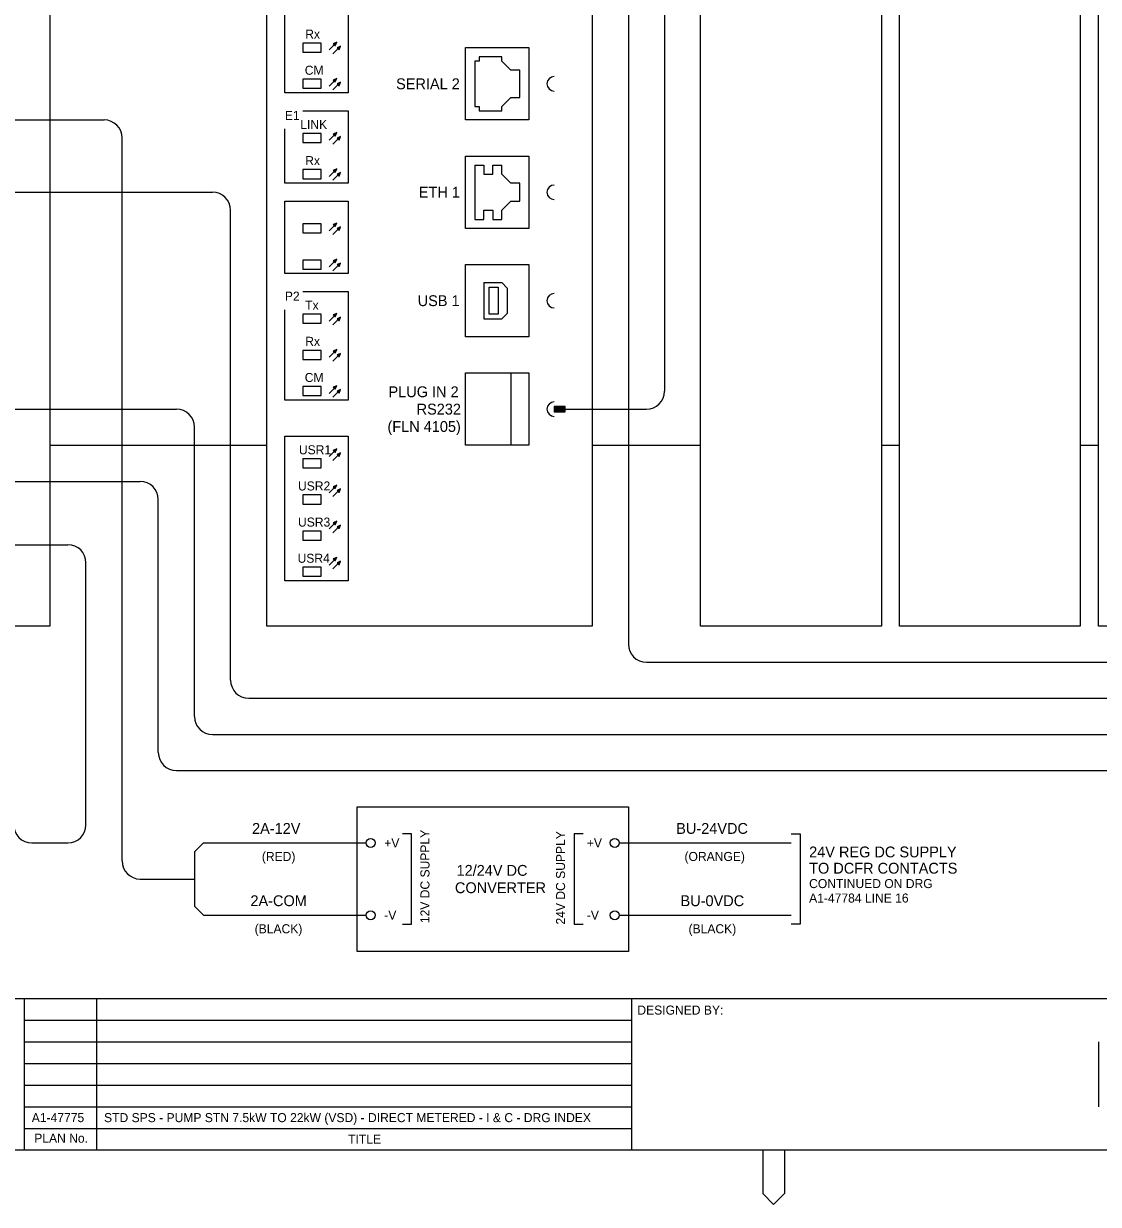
# Model space of a CAD drawing. Extents: x 0 to 841, y 0 to 594.
# Drawn here: x 212.8 to 510, y 0 to 326.6 of the extents above; entities that cross this region are included whole.
import ezdxf

# ---------------------------------------------------------------- set-up
doc = ezdxf.new("R2010")
doc.units = 0
for name, color, linetype in [('A1BORDER', 7, 'Continuous'), ('Level 1', 7, 'Continuous'), ('Level 10', 7, 'Continuous'), ('Level 5', 7, 'Continuous')]:
    doc.layers.add(name, color=color, linetype=linetype)

msp = doc.modelspace()

# ---------------------------------------------------------------- linework, layer by layer
at = {"layer": 'A1BORDER'}
for p, q in [((28, 57), (829, 57)), ((213, 15), (213, 57)), ((233, 15), (233, 57)), ((381, 15), (381, 57)), ((213, 51), (381, 51)), ((213, 45), (381, 45)), ((213, 39), (381, 39)), ((213, 33), (381, 33)), ((213, 27), (381, 27)), ((213, 21), (381, 21)), ((829, 15), (28, 15)), ((417.19, 15), (417.19, 3)), ((423.19, 15), (423.19, 3)), ((417.19, 3), (420.19, 0)), ((423.19, 3), (420.19, 0))]:
    msp.add_line(p, q, dxfattribs=at)
at = {"layer": 'Level 1'}
for p, q in [((390, 555), (390, 225)), ((380, 340), (380, 155)), ((345, 317.5), (338.75, 317.5)), ((338.75, 317.5), (338.75, 316.25)), ((345, 316.25), (345, 317.5)), ((337.5, 316.25), (337.5, 303.75)), ((338.75, 316.25), (337.5, 316.25)), ((345, 316.25), (347.5, 313.75)), ((350, 313.75), (347.5, 313.75)), ((350, 306.25), (350, 313.75)), ((345, 303.75), (347.5, 306.25)), ((347.5, 306.25), (350, 306.25)), ((337.5, 303.75), (338.75, 303.75)), ((338.75, 303.75), (338.75, 302.5)), ((338.75, 302.5), (345, 302.5)), ((345, 302.5), (345, 303.75)), ((207.5, 300), (235, 300)), ((240, 95), (240, 295)), ((337.5, 287.5), (337.5, 272.5)), ((337.5, 287.5), (340, 287.5)), ((340, 287.5), (340, 285)), ((342.5, 285), (342.5, 287.5)), ((342.5, 287.5), (345, 287.5)), ((345, 285), (345, 287.5)), ((340, 285), (342.5, 285)), ((345, 285), (347.5, 282.5)), ((350, 282.5), (347.5, 282.5)), ((350, 277.5), (350, 282.5)), ((207.5, 280), (265, 280)), ((270, 145), (270, 275)), ((340, 272.5), (340, 275)), ((340, 275), (342.5, 275)), ((342.5, 275), (342.5, 272.5)), ((345, 275), (347.5, 277.5)), ((345, 272.5), (345, 275)), ((347.5, 277.5), (350, 277.5)), ((337.5, 272.5), (340, 272.5)), ((342.5, 272.5), (345, 272.5)), ((340, 255), (340, 245)), ((340, 255), (345, 255)), ((345, 255), (346.5, 253.5)), ((346.5, 253.5), (346.5, 246.5)), ((340, 245), (345, 245)), ((345, 245), (346.5, 246.5)), ((347.5, 230), (347.5, 210)), ((207.5, 220), (255, 220)), ((362.5, 220), (385, 220)), ((260, 135), (260, 215)), ((220, 210), (280, 210)), ((370, 210), (400, 210)), ((450, 210), (455, 210)), ((505, 210), (510, 210)), ((207.5, 200), (245, 200)), ((250, 125), (250, 195)), ((207.5, 182.5), (225, 182.5)), ((230, 105), (230, 177.5)), ((385, 150), (585, 150)), ((275, 140), (595, 140)), ((265, 130), (605, 130)), ((255, 120), (685, 120)), ((215, 100), (225, 100)), ((262.5, 100), (260, 97.5)), ((262.5, 100), (307.5, 100)), ((377.5, 100), (425, 100)), ((260, 97.5), (260, 82.5)), ((245, 90), (260.01, 90)), ((262.5, 80), (260, 82.5)), ((262.5, 80), (307.5, 80)), ((377.5, 80), (425, 80))]:
    msp.add_line(p, q, dxfattribs=at)
for points in [[(140, 510), (220, 510), (220, 160), (140, 160)], [(280, 510), (370, 510), (370, 160), (280, 160)], [(400, 510), (450, 510), (450, 160), (400, 160)], [(455, 510), (505, 510), (505, 160), (455, 160)], [(510, 510), (560, 510), (560, 160), (510, 160)], [(295, 321.25), (290, 321.25), (290, 318.75), (295, 318.75)], [(335, 320), (352.5, 320), (352.5, 300), (335, 300)], [(295, 311.25), (290, 311.25), (290, 308.75), (295, 308.75)], [(295, 296.25), (290, 296.25), (290, 293.75), (295, 293.75)], [(335, 290), (352.5, 290), (352.5, 270), (335, 270)], [(295, 286.25), (290, 286.25), (290, 283.75), (295, 283.75)], [(285, 277.5), (302.5, 277.5), (302.5, 257.5), (285, 257.5)], [(295, 271.25), (290, 271.25), (290, 268.75), (295, 268.75)], [(295, 261.25), (290, 261.25), (290, 258.75), (295, 258.75)], [(335, 260), (352.5, 260), (352.5, 240), (335, 240)], [(341.5, 253.75), (344, 253.75), (344, 246.25), (341.5, 246.25)], [(295, 246.25), (290, 246.25), (290, 243.75), (295, 243.75)], [(295, 236.25), (290, 236.25), (290, 233.75), (295, 233.75)], [(335, 230), (352.5, 230), (352.5, 210), (335, 210)], [(295, 226.25), (290, 226.25), (290, 223.75), (295, 223.75)], [(285, 212.5), (302.5, 212.5), (302.5, 172.5), (285, 172.5)], [(295, 206.25), (290, 206.25), (290, 203.75), (295, 203.75)], [(295, 196.25), (290, 196.25), (290, 193.75), (295, 193.75)], [(295, 186.25), (290, 186.25), (290, 183.75), (295, 183.75)], [(295, 176.25), (290, 176.25), (290, 173.75), (295, 173.75)], [(305, 110), (380, 110), (380, 70), (305, 70)]]:
    msp.add_lwpolyline(points, close=True, dxfattribs=at)
for points in [[(290, 337.5), (302.5, 337.5), (302.5, 307.5), (285, 307.5), (285, 332.5)], [(290, 302.5), (302.5, 302.5), (302.5, 282.5), (285, 282.5), (285, 297.5)], [(290, 252.5), (302.5, 252.5), (302.5, 222.5), (285, 222.5), (285, 247.5)], [(317.5, 77.5), (320, 77.5), (320, 102.5), (317.5, 102.5)], [(367.5, 102.5), (365, 102.5), (365, 77.5), (367.5, 77.5)], [(425, 102.5), (427.5, 102.5), (427.5, 77.5), (425, 77.5)]]:
    msp.add_lwpolyline(points, dxfattribs=at)
for centre, start, end in [((235, 295), 0, 90), ((265, 275), 0, 90), ((385, 225), 270, 0), ((255, 215), 0, 90), ((245, 195), 0, 90), ((225, 177.5), 0, 90), ((385, 155), 180, 270), ((275, 145), 180, 270), ((265, 135), 180, 270), ((255, 125), 180, 270), ((215, 105), 180, 270), ((225, 105), 270, 360), ((245, 95), 180, 270)]:
    msp.add_arc(centre, 5, start, end, dxfattribs=at)
at = {"layer": 'Level 10'}
for p, q in [((297.23, 319.36), (299.36, 321.48)), ((298.29, 318.3), (300.42, 320.42)), ((298.46, 321.07), (299.17, 321.07)), ((298.5, 320.93), (299.11, 320.93)), ((298.64, 320.78), (299.04, 320.78)), ((298.79, 321.23), (299.24, 321.23)), ((298.8, 320.62), (298.97, 320.62)), ((299.12, 321.38), (299.31, 321.38)), ((299.85, 320.17), (300.3, 320.17)), ((300.18, 320.31), (300.37, 320.31)), ((299.52, 320.01), (300.23, 320.01)), ((299.56, 319.87), (300.17, 319.87)), ((299.7, 319.72), (300.1, 319.72)), ((299.86, 319.56), (300.03, 319.56)), ((297.23, 309.36), (299.36, 311.48)), ((298.29, 308.3), (300.42, 310.42)), ((298.46, 311.07), (299.17, 311.07)), ((298.5, 310.93), (299.11, 310.93)), ((298.64, 310.78), (299.04, 310.78)), ((298.79, 311.23), (299.24, 311.23)), ((298.8, 310.62), (298.97, 310.62)), ((299.12, 311.38), (299.31, 311.38)), ((299.52, 310.01), (300.23, 310.01)), ((299.56, 309.87), (300.17, 309.87)), ((299.7, 309.72), (300.1, 309.72)), ((299.85, 310.17), (300.3, 310.17)), ((299.86, 309.56), (300.03, 309.56)), ((300.18, 310.31), (300.37, 310.31)), ((297.23, 294.36), (299.36, 296.48)), ((298.29, 293.3), (300.42, 295.42)), ((298.46, 296.07), (299.17, 296.07)), ((298.5, 295.93), (299.11, 295.93)), ((298.64, 295.78), (299.04, 295.78)), ((298.79, 296.23), (299.24, 296.23)), ((298.8, 295.62), (298.97, 295.62)), ((299.12, 296.38), (299.31, 296.38)), ((299.52, 295.01), (300.23, 295.01)), ((299.56, 294.87), (300.17, 294.87)), ((299.7, 294.72), (300.1, 294.72)), ((299.85, 295.17), (300.3, 295.17)), ((299.86, 294.56), (300.03, 294.56)), ((300.18, 295.31), (300.37, 295.31)), ((297.23, 284.36), (299.36, 286.48)), ((298.29, 283.3), (300.42, 285.42)), ((298.46, 286.07), (299.17, 286.07)), ((298.5, 285.93), (299.11, 285.93)), ((298.64, 285.78), (299.04, 285.78)), ((298.79, 286.23), (299.24, 286.23)), ((298.8, 285.62), (298.97, 285.62)), ((299.12, 286.38), (299.31, 286.38)), ((299.52, 285.01), (300.23, 285.01)), ((299.56, 284.87), (300.17, 284.87)), ((299.7, 284.72), (300.1, 284.72)), ((299.85, 285.17), (300.3, 285.17)), ((299.86, 284.56), (300.03, 284.56)), ((300.18, 285.31), (300.37, 285.31)), ((297.23, 269.36), (299.36, 271.48)), ((298.79, 271.23), (299.24, 271.23)), ((299.12, 271.38), (299.31, 271.38)), ((298.29, 268.3), (300.42, 270.42)), ((298.46, 271.07), (299.17, 271.07)), ((298.5, 270.93), (299.11, 270.93)), ((298.64, 270.77), (299.04, 270.77)), ((298.8, 270.62), (298.97, 270.62)), ((299.52, 270.01), (300.23, 270.01)), ((299.56, 269.87), (300.17, 269.87)), ((299.7, 269.72), (300.1, 269.72)), ((299.85, 270.17), (300.3, 270.17)), ((299.86, 269.56), (300.03, 269.56)), ((300.18, 270.31), (300.37, 270.31)), ((297.23, 259.36), (299.36, 261.48)), ((299.12, 261.38), (299.31, 261.38)), ((298.29, 258.3), (300.42, 260.42)), ((298.46, 261.07), (299.17, 261.07)), ((298.5, 260.93), (299.11, 260.93)), ((298.64, 260.77), (299.04, 260.77)), ((298.79, 261.23), (299.24, 261.23)), ((298.8, 260.62), (298.97, 260.62)), ((299.52, 260.01), (300.23, 260.01)), ((299.56, 259.87), (300.17, 259.87)), ((299.7, 259.72), (300.1, 259.72)), ((299.85, 260.17), (300.3, 260.17)), ((299.86, 259.56), (300.03, 259.56)), ((300.18, 260.31), (300.37, 260.31)), ((297.23, 244.36), (299.36, 246.48)), ((298.29, 243.3), (300.42, 245.42)), ((298.46, 246.08), (299.17, 246.08)), ((298.5, 245.93), (299.11, 245.93)), ((298.64, 245.78), (299.04, 245.78)), ((298.79, 246.22), (299.24, 246.22)), ((298.8, 245.62), (298.97, 245.62)), ((299.12, 246.38), (299.31, 246.38)), ((299.52, 245.02), (300.23, 245.02)), ((299.85, 245.16), (300.3, 245.16)), ((300.18, 245.31), (300.37, 245.31)), ((299.56, 244.87), (300.17, 244.87)), ((299.7, 244.72), (300.1, 244.72)), ((299.86, 244.56), (300.03, 244.56)), ((297.23, 234.36), (299.36, 236.48)), ((298.29, 233.3), (300.42, 235.42)), ((298.46, 236.08), (299.17, 236.08)), ((298.5, 235.93), (299.11, 235.93)), ((298.64, 235.78), (299.04, 235.78)), ((298.79, 236.22), (299.24, 236.22)), ((298.8, 235.62), (298.97, 235.62)), ((299.12, 236.38), (299.31, 236.38)), ((300.18, 235.31), (300.37, 235.31)), ((299.52, 235.02), (300.23, 235.02)), ((299.56, 234.87), (300.17, 234.87)), ((299.7, 234.72), (300.1, 234.72)), ((299.85, 235.16), (300.3, 235.16)), ((299.86, 234.56), (300.03, 234.56)), ((297.23, 224.36), (299.36, 226.48)), ((298.29, 223.3), (300.42, 225.42)), ((298.46, 226.08), (299.17, 226.08)), ((298.5, 225.93), (299.11, 225.93)), ((298.64, 225.78), (299.04, 225.78)), ((298.79, 226.22), (299.24, 226.22)), ((298.8, 225.62), (298.97, 225.62)), ((299.12, 226.38), (299.31, 226.38)), ((299.52, 225.02), (300.23, 225.02)), ((299.56, 224.87), (300.17, 224.87)), ((299.7, 224.72), (300.1, 224.72)), ((299.85, 225.16), (300.3, 225.16)), ((299.86, 224.56), (300.03, 224.56)), ((300.18, 225.31), (300.37, 225.31)), ((359.5, 220.5), (362.5, 220.5)), ((359.5, 220.25), (362.5, 220.25)), ((359.5, 220), (362.5, 220)), ((359.5, 219.75), (362.5, 219.75)), ((359.5, 219.5), (362.5, 219.5)), ((297.23, 206.86), (299.36, 208.98)), ((298.29, 205.8), (300.42, 207.92)), ((298.46, 208.58), (299.17, 208.58)), ((298.5, 208.43), (299.11, 208.43)), ((298.64, 208.28), (299.04, 208.28)), ((298.79, 208.72), (299.24, 208.72)), ((298.8, 208.12), (298.97, 208.12)), ((299.12, 208.88), (299.31, 208.88)), ((299.52, 207.52), (300.23, 207.52)), ((299.56, 207.37), (300.17, 207.37)), ((299.7, 207.22), (300.1, 207.22)), ((299.85, 207.66), (300.3, 207.66)), ((299.86, 207.06), (300.03, 207.06)), ((300.18, 207.81), (300.37, 207.81)), ((297.23, 196.86), (299.36, 198.98)), ((298.29, 195.8), (300.42, 197.92)), ((298.46, 198.58), (299.17, 198.58)), ((298.5, 198.43), (299.11, 198.43)), ((298.64, 198.28), (299.04, 198.28)), ((298.79, 198.72), (299.24, 198.72)), ((298.8, 198.12), (298.97, 198.12)), ((299.12, 198.88), (299.31, 198.88)), ((299.52, 197.52), (300.23, 197.52)), ((299.56, 197.37), (300.17, 197.37)), ((299.7, 197.22), (300.1, 197.22)), ((299.85, 197.66), (300.3, 197.66)), ((299.86, 197.06), (300.03, 197.06)), ((300.18, 197.81), (300.37, 197.81)), ((297.23, 186.85), (299.36, 188.98)), ((298.29, 185.8), (300.42, 187.92)), ((298.46, 188.58), (299.17, 188.58)), ((298.5, 188.43), (299.11, 188.43)), ((298.64, 188.28), (299.04, 188.28)), ((298.79, 188.72), (299.24, 188.72)), ((298.8, 188.12), (298.97, 188.12)), ((299.12, 188.88), (299.31, 188.88)), ((299.52, 187.52), (300.23, 187.52)), ((299.56, 187.37), (300.17, 187.37)), ((299.7, 187.22), (300.1, 187.22)), ((299.85, 187.66), (300.3, 187.66)), ((299.86, 187.06), (300.03, 187.06)), ((300.18, 187.81), (300.37, 187.81)), ((297.23, 176.85), (299.36, 178.98)), ((298.29, 175.8), (300.42, 177.92)), ((298.46, 178.58), (299.17, 178.58)), ((298.5, 178.43), (299.11, 178.43)), ((298.64, 178.28), (299.04, 178.28)), ((298.79, 178.72), (299.24, 178.72)), ((298.8, 178.12), (298.97, 178.12)), ((299.12, 178.88), (299.31, 178.88)), ((299.52, 177.52), (300.23, 177.52)), ((299.56, 177.37), (300.17, 177.37)), ((299.7, 177.22), (300.1, 177.22)), ((299.85, 177.66), (300.3, 177.66)), ((299.86, 177.06), (300.03, 177.06)), ((300.18, 177.81), (300.37, 177.81)), ((510, 44.97), (510, 27.03))]:
    msp.add_line(p, q, dxfattribs=at)
for points in [[(299.36, 321.48), (298.38, 321.04), (298.92, 320.5)], [(300.42, 320.42), (299.44, 319.98), (299.98, 319.44)], [(299.36, 311.48), (298.38, 311.04), (298.92, 310.5)], [(300.42, 310.42), (299.44, 309.98), (299.98, 309.44)], [(299.36, 296.48), (298.38, 296.04), (298.92, 295.5)], [(300.42, 295.42), (299.44, 294.98), (299.98, 294.44)], [(299.36, 286.48), (298.38, 286.04), (298.92, 285.5)], [(300.42, 285.42), (299.44, 284.98), (299.98, 284.44)], [(299.36, 271.48), (298.38, 271.04), (298.92, 270.5)], [(300.42, 270.42), (299.44, 269.98), (299.98, 269.44)], [(299.36, 261.48), (298.38, 261.04), (298.92, 260.5)], [(300.42, 260.42), (299.44, 259.98), (299.98, 259.44)], [(299.36, 246.48), (298.38, 246.04), (298.92, 245.5)], [(300.42, 245.42), (299.44, 244.98), (299.98, 244.44)], [(299.36, 236.48), (298.38, 236.04), (298.92, 235.5)], [(300.42, 235.42), (299.44, 234.98), (299.98, 234.44)], [(299.36, 226.48), (298.38, 226.04), (298.92, 225.5)], [(300.42, 225.42), (299.44, 224.98), (299.98, 224.44)], [(359.5, 219.25), (362.5, 219.25), (362.5, 220.75), (359.5, 220.75)], [(299.36, 208.98), (298.38, 208.54), (298.92, 208)], [(300.42, 207.92), (299.44, 207.48), (299.98, 206.94)], [(299.36, 198.98), (298.38, 198.54), (298.92, 198)], [(300.42, 197.92), (299.44, 197.48), (299.98, 196.94)], [(299.36, 188.98), (298.38, 188.54), (298.92, 188)], [(300.42, 187.92), (299.44, 187.48), (299.98, 186.94)], [(299.36, 178.98), (298.38, 178.54), (298.92, 178)], [(300.42, 177.92), (299.44, 177.48), (299.98, 176.94)]]:
    msp.add_lwpolyline(points, close=True, dxfattribs=at)
for centre in [(308.75, 100), (376.25, 100), (308.75, 80), (376.25, 80)]:
    msp.add_circle(centre, 1.25, dxfattribs=at)
for centre in [(359.5, 310), (359.5, 280), (359.5, 250), (359.5, 220)]:
    msp.add_arc(centre, 2, 90, 270, dxfattribs=at)

# ---------------------------------------------------------------- texts
at = {"layer": 'A1BORDER'}
for s, p in [('DESIGNED BY:', (382.5, 52.5)), ('PLAN No.', (215.69, 17.06)), ('TITLE', (302.5, 16.81))]:
    msp.add_text(s, height=2.5, dxfattribs=at).set_placement(p)
at = {"layer": 'Level 1'}
for s, height, p in [('Rx', 2.5, (290.63, 322.5)), ('CM', 2.5, (290.51, 312.5)), ('SERIAL 2', 3, (315.77, 308.5)), ('E1', 2.5, (285, 300)), ('LINK', 2.5, (289.26, 297.5)), ('Rx', 2.5, (290.63, 287.5)), ('ETH 1', 3, (322.04, 278.5)), ('P2', 2.5, (285, 250)), ('USB 1', 3, (321.74, 248.5)), ('Tx', 2.5, (290.63, 247.5)), ('Rx', 2.5, (290.63, 237.5)), ('CM', 2.5, (290.51, 227.5)), ('PLUG IN 2', 3, (313.67, 223.3)), ('RS232', 3, (321.44, 218.5)), ('(FLN 4105)', 3, (313.38, 213.7)), ('USR1', 2.5, (288.89, 207.5)), ('USR2', 2.5, (288.64, 197.5)), ('USR3', 2.5, (288.64, 187.5)), ('USR4', 2.5, (288.52, 177.5)), ('2A-12V', 3, (275.93, 102.5)), ('BU-24VDC', 3, (393.24, 102.5)), ('+V', 2.5, (312.5, 98.75)), ('+V', 2.5, (368.52, 98.75)), ('24V REG DC SUPPLY', 3, (430, 96)), ('12/24V DC', 3, (332.49, 90.9)), ('TO DCFR CONTACTS', 3, (430, 91.5)), ('CONVERTER', 3, (332.04, 86.1)), ('CONTINUED ON DRG', 2.5, (430, 87.5)), ('2A-COM', 3, (275.48, 82.5)), ('BU-0VDC', 3, (394.43, 82.5)), ('A1-47784 LINE 16', 2.5, (430, 83.5)), ('-V', 2.5, (312.5, 78.75)), ('-V', 2.5, (368.52, 78.75)), ('A1-47775', 2.5, (215, 22.75)), ('STD SPS - PUMP STN 7.5kW TO 22kW (VSD) - DIRECT METERED - I & C - DRG INDEX', 2.5, (235, 22.75))]:
    msp.add_text(s, height=height, dxfattribs=at).set_placement(p)
at = {"layer": 'Level 5'}
for s, p in [('12V DC SUPPLY', (325, 77.8)), ('24V DC SUPPLY', (362.5, 77.42))]:
    msp.add_text(s, height=2.5, rotation=90, dxfattribs=at).set_placement(p)
for s, p in [('(RED)', (278.64, 95)), ('(ORANGE)', (395.53, 95)), ('(BLACK)', (276.65, 75)), ('(BLACK)', (396.65, 75))]:
    msp.add_text(s, height=2.5, dxfattribs=at).set_placement(p)

doc.saveas('drawing.dxf')
